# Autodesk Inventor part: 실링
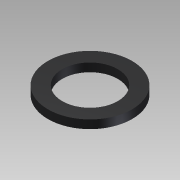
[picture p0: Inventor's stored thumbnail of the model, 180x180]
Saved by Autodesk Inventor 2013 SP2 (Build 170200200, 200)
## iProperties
Created: 2025-04
Part Number: 실링
Material: Generic
Document SubType Name: Modeling
Designer: i
Density: 1 g/cm^3
변환 표준: STEP AP214IS
전처리기: Build: 200, Release: 2013 SP2 Update 6 - Date: Thu 07/17/2014
전송 단위: 밀리미터
불확실성: 0.01
Author: i
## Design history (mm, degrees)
node "실링1"
node "솔리드1"
node "기준1"
